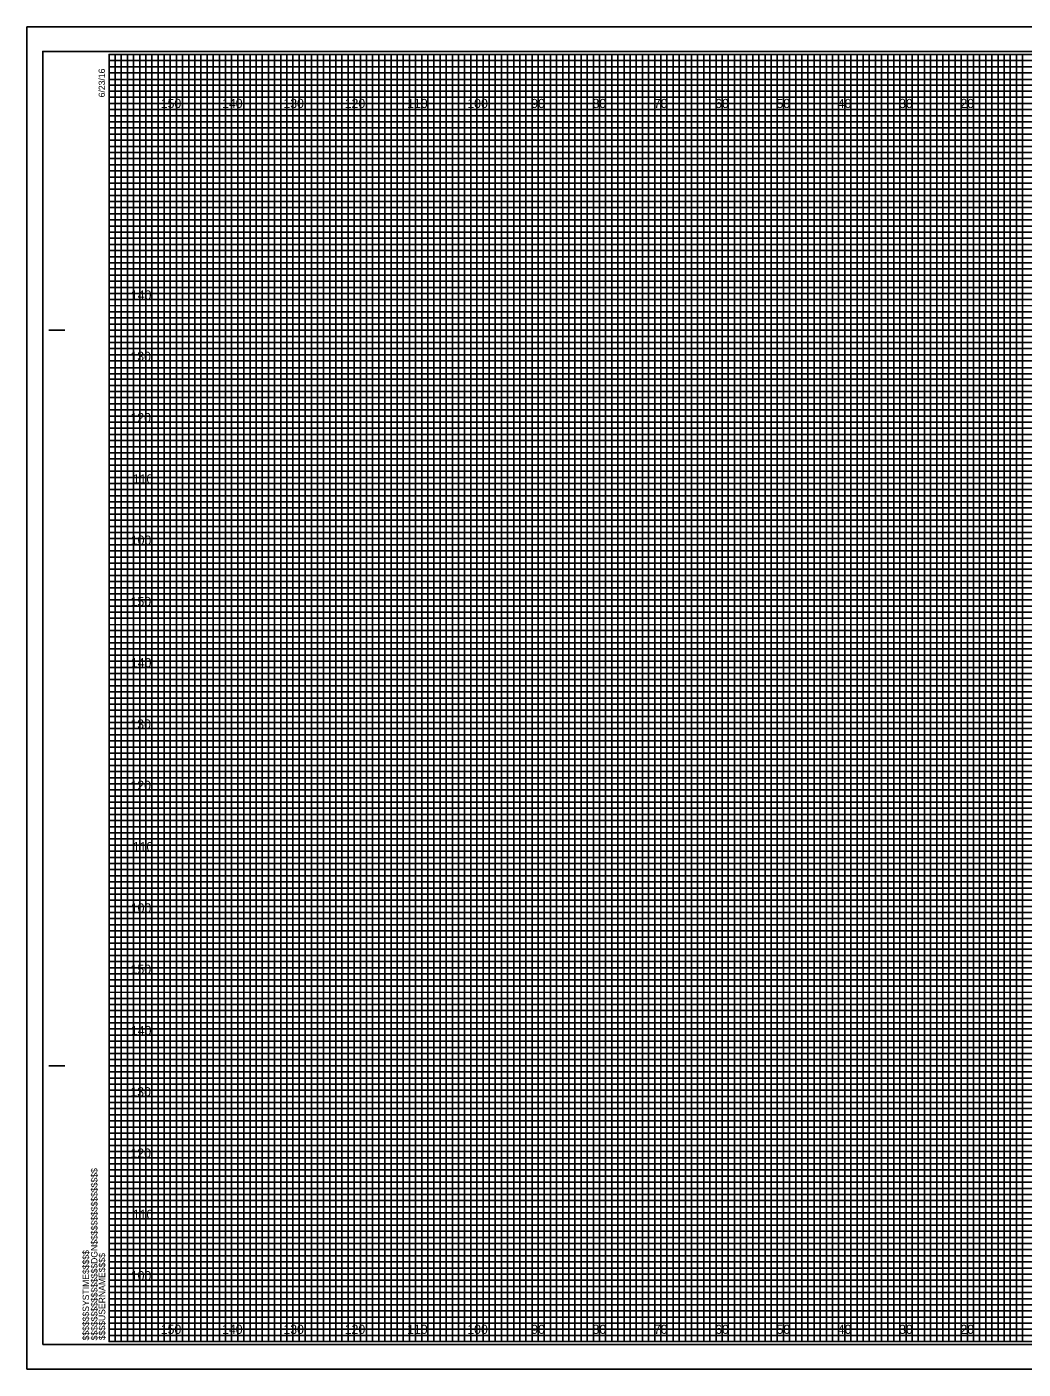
# Model space of a CAD drawing. Extents: x -13 to 323, y -5 to 2634.
# Drawn here: x -13.4 to 149.1, y 1975.5 to 2194.5 of the extents above; entities that cross this region are included whole.
import ezdxf

# ---------------------------------------------------------------- set-up
doc = ezdxf.new("R2010")
doc.units = 0
for name, color, linetype in [('Exist Cross Section Cell', 7, 'Continuous'), ('Exist XS Center Line Elevation Label', 7, 'Continuous'), ('Exist XS Ground Line', 7, 'Continuous'), ('Prop CMT Pvmt Course 1 Wedge', 7, 'Continuous'), ('Prop CMT Pvmt Course 2', 7, 'Continuous'), ('Prop CMT Pvmt Course 2 Wedge', 7, 'Continuous'), ('Prop CMT Pvmt Course 3', 7, 'Continuous'), ('Prop CMT Shld Paved Course 1', 7, 'Continuous'), ('Prop CMT Shld Paved Course 2', 7, 'Continuous'), ('Prop CMT Subgrade Earthwork', 7, 'Continuous'), ('Scratch_Level_0', 7, 'Continuous')]:
    doc.layers.add(name, color=color, linetype=linetype)

msp = doc.modelspace()

# ---------------------------------------------------------------- linework, layer by layer
at = {"layer": 'Exist XS Center Line Elevation Label'}
for points in [[(0, 2190), (5, 2190), (5, 1980), (15, 1980), (15, 2190), (25, 2190), (25, 1980), (35, 1980), (35, 2190), (45, 2190), (45, 1980), (55, 1980), (55, 2190), (65, 2190), (65, 1980), (75, 1980), (75, 2190), (85, 2190), (85, 1980), (95, 1980), (95, 2190), (105, 2190), (105, 1980), (115, 1980), (115, 2190), (125, 2190), (125, 1980), (135, 1980), (135, 2190), (145, 2190), (145, 1980), (155, 1980)], [(0, 2185), (275, 2185)], [(0, 2165), (320, 2165), (320, 2175), (0, 2175)], [(0, 2145), (320, 2145), (320, 2155), (0, 2155)], [(0, 2125), (320, 2125), (320, 2135), (0, 2135)], [(0, 2105), (320, 2105), (320, 2115), (0, 2115)], [(0, 2085), (320, 2085), (320, 2095), (0, 2095)], [(0, 2065), (320, 2065), (320, 2075), (0, 2075)], [(0, 2045), (320, 2045), (320, 2055), (0, 2055)], [(0, 2025), (320, 2025), (320, 2035), (0, 2035)], [(0, 2005), (320, 2005), (320, 2015), (0, 2015)], [(0, 1985), (320, 1985), (320, 1995), (0, 1995)]]:
    msp.add_lwpolyline(points, dxfattribs=at)
at = {"layer": 'Exist XS Ground Line'}
for p, q in [((10, 2190), (0, 2190)), ((10, 1980), (10, 2190)), ((30, 2190), (20, 2190)), ((20, 2190), (20, 1980)), ((30, 1980), (30, 2190)), ((50, 2190), (40, 2190)), ((40, 2190), (40, 1980)), ((50, 1980), (50, 2190)), ((70, 2190), (60, 2190)), ((60, 2190), (60, 1980)), ((70, 1980), (70, 2190)), ((90, 2190), (80, 2190)), ((80, 2190), (80, 1980)), ((90, 1980), (90, 2190)), ((110, 2190), (100, 2190)), ((100, 2190), (100, 1980)), ((110, 1980), (110, 2190)), ((130, 2190), (120, 2190)), ((120, 2190), (120, 1980)), ((130, 1980), (130, 2190)), ((150, 2190), (140, 2190)), ((140, 2190), (140, 1980)), ((20, 1980), (10, 1980)), ((40, 1980), (30, 1980)), ((60, 1980), (50, 1980)), ((80, 1980), (70, 1980)), ((100, 1980), (90, 1980)), ((120, 1980), (110, 1980)), ((140, 1980), (130, 1980))]:
    msp.add_line(p, q, dxfattribs=at)
for points in [[(0, 2180), (320, 2180), (320, 2170), (0, 2170)], [(0, 2160), (320, 2160), (320, 2150), (0, 2150)], [(0, 2140), (320, 2140), (320, 2130), (0, 2130)], [(0, 2120), (320, 2120), (320, 2110), (0, 2110)], [(0, 2100), (320, 2100), (320, 2090), (0, 2090)], [(0, 2080), (320, 2080), (320, 2070), (0, 2070)], [(0, 2060), (320, 2060), (320, 2050), (0, 2050)], [(0, 2040), (320, 2040), (320, 2030), (0, 2030)], [(0, 2020), (320, 2020), (320, 2010), (0, 2010)], [(0, 2000), (320, 2000), (320, 1990), (0, 1990)]]:
    msp.add_lwpolyline(points, dxfattribs=at)
at = {"layer": 'Prop CMT Pvmt Course 1 Wedge'}
for p, q in [((323.3, 2194.5), (-13.4, 2194.5)), ((-13.4, 2194.5), (-13.4, 1975.5)), ((-13.4, 1975.5), (323.3, 1975.5))]:
    msp.add_line(p, q, dxfattribs=at)
at = {"layer": 'Prop CMT Pvmt Course 2'}
msp.add_lwpolyline([(-13.4, 1975.5), (323.3, 1975.5), (323.3, 2194.5), (-13.4, 2194.5)], close=True, dxfattribs=at)
at = {"layer": 'Prop CMT Pvmt Course 3'}
msp.add_lwpolyline([(-10.8, 1979.5), (322.4, 1979.5), (322.4, 2190.5), (-10.8, 2190.5)], close=True, dxfattribs=at)
at = {"layer": 'Prop CMT Shld Paved Course 1'}
for p, q in [((-9.8, 2145), (-7.3, 2145)), ((-9.7, 2145), (-7.2, 2145)), ((-9.8, 2025), (-7.3, 2025)), ((-9.7, 2025), (-7.2, 2025)), ((0, 1980), (0, 1980)), ((0, 1980), (0, 1980)), ((0, 1980), (0, 1980)), ((0, 1980), (0, 1980)), ((0, 1980), (0, 1980)), ((0, 1980), (0, 1980)), ((0, 1980), (0, 1980))]:
    msp.add_line(p, q, dxfattribs=at)
msp.add_lwpolyline([(320, 2190), (0, 2190), (0, 1980), (320, 1980)], close=True, dxfattribs=at)
at = {"layer": 'Prop CMT Shld Paved Course 2'}
for points in [[(0, 1980), (1, 1980), (1, 2190), (2, 2190), (2, 1980)], [(2, 1980), (3, 1980), (3, 2190), (4, 2190), (4, 1980)], [(5, 1980), (6, 1980), (6, 2190), (7, 2190), (7, 1980)], [(7, 1980), (8, 1980), (8, 2190), (9, 2190), (9, 1980)], [(10, 1980), (11, 1980), (11, 2190), (12, 2190), (12, 1980)], [(12, 1980), (13, 1980), (13, 2190), (14, 2190), (14, 1980)], [(15, 1980), (16, 1980), (16, 2190), (17, 2190), (17, 1980)], [(17, 1980), (18, 1980), (18, 2190), (19, 2190), (19, 1980)], [(20, 1980), (21, 1980), (21, 2190), (22, 2190), (22, 1980)], [(22, 1980), (23, 1980), (23, 2190), (24, 2190), (24, 1980)], [(25, 1980), (26, 1980), (26, 2190), (27, 2190), (27, 1980)], [(27, 1980), (28, 1980), (28, 2190), (29, 2190), (29, 1980)], [(30, 1980), (31, 1980), (31, 2190), (32, 2190), (32, 1980)], [(32, 1980), (33, 1980), (33, 2190), (34, 2190), (34, 1980)], [(35, 1980), (36, 1980), (36, 2190), (37, 2190), (37, 1980)], [(37, 1980), (38, 1980), (38, 2190), (39, 2190), (39, 1980)], [(40, 1980), (41, 1980), (41, 2190), (42, 2190), (42, 1980)], [(42, 1980), (43, 1980), (43, 2190), (44, 2190), (44, 1980)], [(45, 1980), (46, 1980), (46, 2190), (47, 2190), (47, 1980)], [(47, 1980), (48, 1980), (48, 2190), (49, 2190), (49, 1980)], [(50, 1980), (51, 1980), (51, 2190), (52, 2190), (52, 1980)], [(52, 1980), (53, 1980), (53, 2190), (54, 2190), (54, 1980)], [(55, 1980), (56, 1980), (56, 2190), (57, 2190), (57, 1980)], [(57, 1980), (58, 1980), (58, 2190), (59, 2190), (59, 1980)], [(60, 1980), (61, 1980), (61, 2190), (62, 2190), (62, 1980)], [(62, 1980), (63, 1980), (63, 2190), (64, 2190), (64, 1980)], [(65, 1980), (66, 1980), (66, 2190), (67, 2190), (67, 1980)], [(67, 1980), (68, 1980), (68, 2190), (69, 2190), (69, 1980)], [(70, 1980), (71, 1980), (71, 2190), (72, 2190), (72, 1980)], [(72, 1980), (73, 1980), (73, 2190), (74, 2190), (74, 1980)], [(75, 1980), (76, 1980), (76, 2190), (77, 2190), (77, 1980)], [(77, 1980), (78, 1980), (78, 2190), (79, 2190), (79, 1980)], [(80, 1980), (81, 1980), (81, 2190), (82, 2190), (82, 1980)], [(82, 1980), (83, 1980), (83, 2190), (84, 2190), (84, 1980)], [(85, 1980), (86, 1980), (86, 2190), (87, 2190), (87, 1980)], [(87, 1980), (88, 1980), (88, 2190), (89, 2190), (89, 1980)], [(90, 1980), (91, 1980), (91, 2190), (92, 2190), (92, 1980)], [(92, 1980), (93, 1980), (93, 2190), (94, 2190), (94, 1980)], [(95, 1980), (96, 1980), (96, 2190), (97, 2190), (97, 1980)], [(97, 1980), (98, 1980), (98, 2190), (99, 2190), (99, 1980)], [(100, 1980), (101, 1980), (101, 2190), (102, 2190), (102, 1980)], [(102, 1980), (103, 1980), (103, 2190), (104, 2190), (104, 1980)], [(105, 1980), (106, 1980), (106, 2190), (107, 2190), (107, 1980)], [(107, 1980), (108, 1980), (108, 2190), (109, 2190), (109, 1980)], [(110, 1980), (111, 1980), (111, 2190), (112, 2190), (112, 1980)], [(112, 1980), (113, 1980), (113, 2190), (114, 2190), (114, 1980)], [(115, 1980), (116, 1980), (116, 2190), (117, 2190), (117, 1980)], [(117, 1980), (118, 1980), (118, 2190), (119, 2190), (119, 1980)], [(120, 1980), (121, 1980), (121, 2190), (122, 2190), (122, 1980)], [(122, 1980), (123, 1980), (123, 2190), (124, 2190), (124, 1980)], [(125, 1980), (126, 1980), (126, 2190), (127, 2190), (127, 1980)], [(127, 1980), (128, 1980), (128, 2190), (129, 2190), (129, 1980)], [(130, 1980), (131, 1980), (131, 2190), (132, 2190), (132, 1980)], [(132, 1980), (133, 1980), (133, 2190), (134, 2190), (134, 1980)], [(135, 1980), (136, 1980), (136, 2190), (137, 2190), (137, 1980)], [(137, 1980), (138, 1980), (138, 2190), (139, 2190), (139, 1980)], [(140, 1980), (141, 1980), (141, 2190), (142, 2190), (142, 1980)], [(142, 1980), (143, 1980), (143, 2190), (144, 2190), (144, 1980)], [(145, 1980), (146, 1980), (146, 2190), (147, 2190), (147, 1980)], [(147, 1980), (148, 1980), (148, 2190), (149, 2190), (149, 1980)]]:
    msp.add_lwpolyline(points, dxfattribs=at)
at = {"layer": 'Prop CMT Subgrade Earthwork'}
for p, q in [((10, 1980), (10, 2190)), ((20, 1980), (20, 2190)), ((30, 1980), (30, 2190)), ((40, 1980), (40, 2190)), ((50, 1980), (50, 2190)), ((60, 1980), (60, 2190)), ((70, 1980), (70, 2190)), ((80, 1980), (80, 2190)), ((90, 1980), (90, 2190)), ((100, 1980), (100, 2190)), ((110, 1980), (110, 2190)), ((120, 1980), (120, 2190)), ((130, 1980), (130, 2190)), ((140, 1980), (140, 2190)), ((0, 2180), (320, 2180)), ((0, 2170), (320, 2170)), ((0, 2160), (320, 2160)), ((0, 2150), (320, 2150)), ((0, 2140), (320, 2140)), ((0, 2130), (320, 2130)), ((0, 2120), (320, 2120)), ((0, 2110), (320, 2110)), ((0, 2100), (320, 2100)), ((0, 2090), (320, 2090)), ((0, 2080), (320, 2080)), ((0, 2070), (320, 2070)), ((0, 2060), (320, 2060)), ((0, 2050), (320, 2050)), ((0, 2040), (320, 2040)), ((0, 2030), (320, 2030)), ((0, 2020), (320, 2020)), ((0, 2010), (320, 2010)), ((0, 2000), (320, 2000)), ((0, 1990), (320, 1990))]:
    msp.add_line(p, q, dxfattribs=at)
at = {"layer": 'Scratch_Level_0'}
for p, q in [((0, 2189), (260, 2189)), ((260, 2187.98), (0, 2187.98)), ((0, 2187.98), (0, 2187)), ((0, 2187), (260, 2187)), ((260, 2185.89), (0, 2185.89)), ((0, 2185.89), (0, 2184)), ((0, 2184), (320, 2184))]:
    msp.add_line(p, q, dxfattribs=at)
for points in [[(0, 2183), (270, 2183), (320, 2183), (320, 2182), (0, 2182)], [(0, 2181), (320, 2181), (320, 2179), (0, 2179)], [(0, 2178), (320, 2178), (320, 2177), (0, 2176.98)], [(0, 2176), (320, 2176), (320, 2174), (0, 2174)], [(0, 2173), (320, 2173), (320, 2172), (0, 2172)], [(0, 2171), (320, 2171), (320, 2169), (0, 2169)], [(0, 2168), (320, 2168), (320, 2167), (0, 2167)], [(0, 2166), (320, 2166), (320, 2164), (0, 2164)], [(0, 2163), (320, 2163), (320, 2162), (0, 2162)], [(0, 2161), (320, 2161), (320, 2159), (0, 2159)], [(0, 2158), (320, 2158), (320, 2157), (0, 2157)], [(0, 2156), (320, 2156), (320, 2153.95), (320, 2153), (320, 2152), (0, 2152)], [(0, 2154), (320, 2154), (320, 2153), (0, 2153)], [(0, 2151), (320, 2151), (320, 2149), (0, 2149.03)], [(0, 2149.03), (320, 2149), (320, 2148), (0, 2148)], [(0, 2147), (320, 2147), (320, 2146), (0, 2146)], [(0, 2144), (320, 2144), (320, 2143), (0, 2143)], [(0, 2142), (320, 2142), (320, 2141), (0, 2141)], [(-0.07, 2138.89), (320, 2138.89), (320, 2137.88), (-0.07, 2137.88)], [(0, 2137), (320, 2137), (320, 2136), (0, 2136)], [(0, 2134), (320, 2134), (320, 2133), (0, 2133)], [(0, 2132), (320, 2132), (320, 2131), (0, 2131)], [(0, 2129), (320, 2129), (320, 2128), (0, 2128)], [(0, 2127), (320, 2127), (320, 2126), (0, 2126)], [(0, 2124), (320, 2124), (320, 2123), (0, 2123)], [(0, 2122), (320, 2122), (320, 2121), (0, 2121)], [(0, 2119), (320, 2119), (319.99, 2117.98), (0, 2118)], [(0, 2117), (320, 2117), (320, 2116), (0, 2116)], [(0, 2114), (320, 2114), (320, 2113), (0, 2113)], [(0, 2112), (320, 2112), (320, 2111), (0, 2111)], [(0, 2109), (320, 2109), (320, 2108), (0, 2108)], [(0, 2107), (320, 2107), (320, 2106), (0, 2106)], [(0, 2104), (320, 2104), (320, 2103), (0, 2103)], [(0, 2102), (320, 2102), (320, 2101), (0, 2101)], [(0, 2099), (320, 2099), (320, 2098), (0, 2098)], [(0, 2096.99), (320.07, 2096.91), (320, 2096), (0, 2096)], [(0, 2094), (320, 2094), (320, 2093), (0, 2093)], [(0, 2092), (320, 2092), (320, 2091), (0, 2091)], [(0, 2089), (320, 2089), (320, 2088), (0, 2088)], [(0, 2087), (320, 2087), (320, 2086), (0, 2086)], [(0, 2084), (320, 2084), (320, 2083), (0, 2083)], [(0, 2082), (320, 2082), (320, 2081), (0, 2081)], [(0, 2079), (320, 2079), (320, 2078), (0, 2078)], [(0, 2077), (320, 2077), (320, 2076), (0, 2076)], [(0, 2074), (320, 2074), (320, 2073), (0, 2073)], [(0, 2072), (320, 2072), (320, 2071), (0, 2071)], [(0, 2069), (320, 2069), (320, 2068), (0, 2068)], [(0, 2067), (320, 2067), (320, 2066), (0, 2066)], [(0, 2064), (320, 2064), (320, 2063), (0, 2063)], [(0, 2062), (320, 2062), (320, 2061), (0, 2061)], [(0, 2059), (320, 2059), (319.99, 2057.98), (0, 2058)], [(0, 2057), (320, 2057), (320, 2056), (0, 2056)], [(0, 2054), (320, 2054), (320, 2053), (0, 2053)], [(0, 2052), (320, 2052), (320, 2051), (0, 2051)], [(0, 2049), (320, 2049), (320, 2048), (0, 2048)], [(0, 2047), (320, 2047), (320, 2046), (0, 2046)], [(0, 2044), (320, 2044), (320, 2043), (0, 2043)], [(0, 2042), (320, 2042), (320, 2041), (0, 2041)], [(0, 2039), (320, 2039), (320, 2038), (0, 2038)], [(0, 2036.99), (320.07, 2036.91), (320, 2036), (0, 2036)], [(0, 2034), (320, 2034), (320, 2033), (0, 2033)], [(0, 2032), (320, 2032), (320, 2031), (0, 2031)], [(0, 2029), (320, 2029), (320, 2028), (0, 2028)], [(0, 2027), (320, 2027), (320, 2026), (0, 2026)], [(0, 2024), (320, 2024), (320, 2023), (0, 2023)], [(0, 2022), (320, 2022), (320, 2021), (0, 2021)], [(0, 2019), (320, 2019), (320, 2018), (0, 2018)], [(0, 2017), (320, 2017), (320, 2016), (0, 2016)], [(0, 2014), (320, 2014), (320, 2013), (0, 2013)], [(0, 2012), (320, 2012), (320, 2011), (0, 2011)], [(0, 2009), (320, 2009), (320, 2008), (0, 2008)], [(0, 2007), (320, 2007), (320, 2006), (0, 2006)], [(0, 2004), (320, 2004), (320, 2003), (0, 2003)], [(0, 2002), (320, 2002), (320, 2001), (0, 2001)], [(0, 1999), (320, 1999), (320, 1998), (0, 1998)], [(0, 1997), (320, 1997), (320, 1996), (0, 1996)], [(0, 1994), (320, 1994), (320, 1993), (0, 1993)], [(0, 1992), (320, 1992), (320, 1991), (0, 1991)], [(0, 1989), (320, 1989), (320, 1988), (0, 1988)], [(0, 1987), (320, 1987), (320, 1986), (0, 1986)], [(0, 1984), (320, 1984), (320, 1983), (0, 1983)], [(0, 1982), (320, 1982), (320, 1981), (0, 1981)]]:
    msp.add_lwpolyline(points, dxfattribs=at)

# ---------------------------------------------------------------- texts
at = {"layer": 'Exist Cross Section Cell'}
for s, p in [('150', (8.44, 2181.25)), ('140', (18.44, 2181.25)), ('130', (28.44, 2181.25)), ('120', (38.44, 2181.25)), ('110', (48.62, 2181.25)), ('100', (58.44, 2181.25)), ('90', (68.86, 2181.25)), ('80', (78.86, 2181.25)), ('70', (88.86, 2181.25)), ('60', (98.86, 2181.25)), ('50', (108.86, 2181.25)), ('40', (118.86, 2181.25)), ('30', (128.86, 2181.25)), ('20', (138.86, 2181.25)), ('150', (8.44, 1981.25)), ('140', (18.44, 1981.25)), ('130', (28.44, 1981.25)), ('120', (38.44, 1981.25)), ('110', (48.62, 1981.25)), ('100', (58.44, 1981.25)), ('90', (68.86, 1981.25)), ('80', (78.86, 1981.25)), ('70', (88.86, 1981.25)), ('60', (98.86, 1981.25)), ('50', (108.86, 1981.25)), ('40', (118.86, 1981.25)), ('30', (128.86, 1981.25)), ('20', (138.86, 1981.25))]:
    msp.add_text(s, height=1.5, dxfattribs=at).set_placement(p)
at = {"layer": 'Prop CMT Pvmt Course 2 Wedge'}
for s, p in [('140', (3.57, 2150)), ('130', (3.49, 2140)), ('120', (3.5, 2130)), ('110', (3.88, 2120)), ('100', (3.55, 2110)), ('150', (3.52, 2100)), ('140', (3.57, 2090)), ('130', (3.49, 2080)), ('120', (3.5, 2070)), ('110', (3.88, 2060)), ('100', (3.55, 2050)), ('150', (3.52, 2040)), ('140', (3.57, 2030)), ('130', (3.49, 2020)), ('120', (3.5, 2010)), ('110', (3.88, 2000)), ('100', (3.55, 1990))]:
    msp.add_text(s, height=1.5, dxfattribs=at).set_placement(p)
at = {"layer": 'Prop CMT Shld Paved Course 1'}
for s, p in [('6/23/16', (-0.65, 2183)), ('$$$$$$$$$$$$$$$$DGN$$$$$$$$$$$$$$$$', (-1.88, 1980.18)), ('$$$$$$SYSTIME$$$$$', (-3.26, 1980.18)), ('$$$$USERNAME$$$$', (-0.62, 1980.23))]:
    msp.add_text(s, height=1.05, rotation=90, dxfattribs=at).set_placement(p)

doc.saveas('drawing.dxf')
